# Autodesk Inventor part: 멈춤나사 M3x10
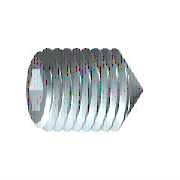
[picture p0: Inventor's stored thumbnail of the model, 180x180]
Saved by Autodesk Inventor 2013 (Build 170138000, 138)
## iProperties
Created: 2012-02
Part Number: 멈춤나사 M3x10
Material: 강철, 연강
Description: 6각 소켓 머리 없는 멈춤 나사
Document SubType Name: Modeling
Standard: KS B 1028
Designer: mduedu
Standards Organization: KS
Language: ko-KR
Size Designation: 원추점 M3x10
Categories: <MemberInstance><Categories><Category DisplayName="조임쇠" InternalName="e4da775c-781d-43d5-af7c-5136215cf5a6" Mnemonic="FSTN"><Category DisplayName="볼트" InternalN
Density: 7.86 g/cm^3
Mass: 0.471457 g
Surface Area: 1.07667 cm^2
Volume: 0.0599818 cm^3
IsCustomPart: 1
Author: mduedu
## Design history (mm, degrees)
sketch "스케치1"
  geometry: L1 (0, 0)-(7.5, 0); L2 (10, 0.866)-(10, 1.5); L3 (10, 1.5)-(0, 1.5); L4 (10, 0.866)-(8, 0.866); L5 (8, 0.866)-(7.5, 0); L6 (0, -0.3)-(0, 1.8) reference; L7 (0, 1.5)-(0, 0)
  constraints: 13 end point, 3 parallel, 1 collinear, 1 perpendicular, 1 point on line
  dimensions: "d0" = 2 distance of L2.start L4.end (= INTI); "d1" = 60 deg angle of L5 L1; "d2" = 3 diameter of L3 L1 (= NND); "d3" = 1.73205 diameter of L4 L1 (= 1.1547 x SW); "d5" = 10 distance from line of L2 L3.end (= NLG)
revolve "본체" sketch "스케치1" stored, may be unused: angle "d6" = 90 deg
sketch "스케치2"
  geometry: L1 (-0.433, 0.75)-(0.433, 0.75); L2 (0.433, 0.75)-(0.866, 0); L3 (0.866, 0)-(0.433, -0.75); L4 (0.433, -0.75)-(-0.433, -0.75); L5 (-0.433, -0.75)-(-0.866, 0); L6 (-0.866, 0)-(-0.433, 0.75); 3 further points
  constraints: 12 end point, 1 coincident, 1 horizontal, 13 other
extrude "슬롯" join sketch "스케치2" taper "d7" = 0 deg; stored distance "d21" = 10
workaxis "Work Axis1"
workplane "Work Plane1"
sketch "스케치4"
  geometry: L1 (4.693, 1.5)-(5, 1.193) reference; L2 (5, 1.193)-(5, 0.866) reference; L3 (5, 0.866)-(3, 0.866) reference; L4 (3, 0.866)-(2.5, 0) reference; L5 (2.5, 0)-(3, -0.866) reference; L6 (3, -0.866)-(5, -0.866) reference; L7 (5, -0.866)-(5, -1.193) reference; L8 (5, -1.193)-(4.693, -1.5) reference; L9 (4.693, -1.5)-(-3.65, -1.5) reference; L10 (-3.65, -1.5)-(-5, -0.15) reference; L11 (-5, -0.15)-(-5, 0.15) reference; L12 (-5, 0.15)-(-3.65, 1.5) reference; L13 (-3.65, 1.5)-(4.693, 1.5) reference; L14 (-3.65, 1.5)-(-5.15, 0); L15 (-3.65, -1.5)-(-5.15, 0); 1 further point
  constraints: 4 end point, 2 collinear
  node "절단 모서리 투영1"
node "작업점1"
body "Solid1"
feature "스레드" dims "d12" = 10 (= NLG), "d13" = 0
chamfer "모따기1" distance "d8" = 1.35 (computed from NND, SPD, FAWI); stored, may be unused: angle "d9" = 45 deg (= FAWI), second distance "d34" = 1.35 (computed from NND, SPD, FAWI)
chamfer "모따기2" distance "d10" = 0.30673 (= -0.5 x GD1 + 0.5 x NND); stored, may be unused: angle "d11" = 45 deg (= FAWI), second distance "d35" = 0.30673 (= -0.5 x GD1 + 0.5 x NND)
other parameters: "NND" = 3 [user parameter; used in 5 equation terms], "NLG" = 10 [user parameter; used in 2 equation terms], "INTI" = 2 [user parameter; used in 1 equation term], "FAWI" = 45 deg [user parameter; used in 4 equation terms], "SW" = 1.5 [user parameter; used in 2 equation terms], "GD1" = 2.38655 (= THREADDIA - 1.2269 x PTC) [user parameter; used in 2 equation terms], "d4" = 0, "FAWI1" = 45 deg [user parameter], "SPD" = 0.3 [user parameter; used in 2 equation terms], "d36" = 0, "d37" = 0, "GUL" = 0.30673 (= 0.61345 x PTC) [user parameter], "TOA" = 30 deg [user parameter], "THREADDIA" = 3 [user parameter; used in 1 equation term], "PTC" = 0.5 [user parameter; used in 4 equation terms], "GAL" = 0.30673 (= 0.61345 x PTC) [user parameter], "E0" = 1.7325 (= 1.155 x SW) [user parameter]
